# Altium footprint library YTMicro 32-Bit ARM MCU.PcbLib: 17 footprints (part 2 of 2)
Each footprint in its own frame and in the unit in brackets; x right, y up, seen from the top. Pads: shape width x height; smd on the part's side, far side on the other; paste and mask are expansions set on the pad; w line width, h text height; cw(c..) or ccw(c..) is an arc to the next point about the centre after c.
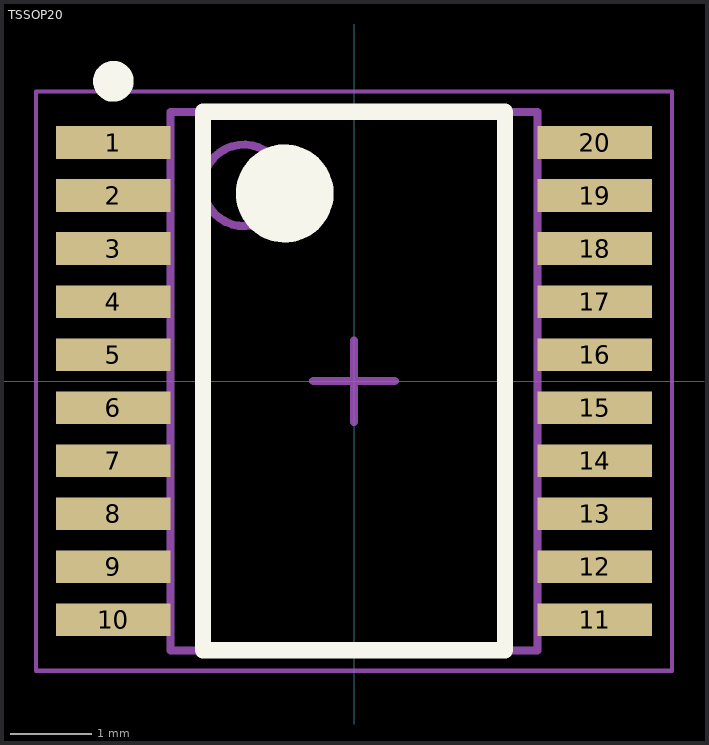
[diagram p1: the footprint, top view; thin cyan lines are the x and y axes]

## TSSOP20 [mm] "TSOP, 20-Leads, Body 6.50x4.40mm, Pitch 0.65mm, IPC Medium Density"
height 1.2
pads (20):
  rect 1.4x0.4 smd: 1(-2.95,2.925) 2(-2.95,2.275) 3(-2.95,1.625) 4(-2.95,0.975) 5(-2.95,0.325) 6(-2.95,-0.325) 7(-2.95,-0.975) 8(-2.95,-1.625) 9(-2.95,-2.275) 10(-2.95,-2.925) 11(2.95,-2.925) 12(2.95,-2.275) 13(2.95,-1.625) 14(2.95,-0.975) 15(2.95,-0.325) 16(2.95,0.325) 17(2.95,0.975) 18(2.95,1.625) 19(2.95,2.275) 20(2.95,2.925)
Top Overlay:
  circle w0.25: c-2.95,3.675 r0.125
  circle w0.6: c-0.85,2.3 r0.3
  lines w0.2: -1.85,-3.3 -1.85,3.3 1.85,3.3 1.85,-3.3 -1.85,-3.3
Mechanical 13:
  circle w0.1: c-1.35,2.4 r0.5
  lines w0.1: -2.25,-3.3 -2.25,3.3 2.25,3.3 2.25,-3.3 -2.25,-3.3
Mechanical 15:
  lines w0.05: -3.9,-3.55 -3.9,3.55 3.9,3.55 3.9,-3.55 -3.9,-3.55
  lines w0.1: -0.5,0 0.5,0 ; 0,-0.5 0,0.5
3D body "TSSOP20.stp": height 1.1, standoff 0, extent -3.2,-3.25 3.2,3.25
